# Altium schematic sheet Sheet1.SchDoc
size OrCAD D; SheetNumber: 1; SheetTotal: 1; SPICEModelCacheXSFJVCKC: <root> / <DocumentId>XSFJVCKC</DocumentId> / <CacheFrame Number="0"> / <Model Name="cap" Kind="MDL"> / <Text>*Default semiconductor capacitor / .MODEL CAP C()</Text> / </Model> / <Model Name="zener" Kind="MDL"> / <Text>*ZENER / *Default Zener 10V @ 10mA / *Zener Diode Pinout: A,K / .MODEL ZENER D( BV=10 IBV=10E-3 )</Text> / </Model> / <Model Name="led1" Kind="MDL"> / <Text>*Typ RED GaAs LED: Vf=1.7V Vr=4V If=40mA trr=3uS / *LED Pinout: 1=A, 2=K / .MODEL LED1 D (IS=93.2P RS=42M N=3.73 BV=4 IBV=10U / + CJO=2.97P VJ=.75 M=.333 TT=4.32U)</Text> / </Model> / <Model Name="1n4007" Kind="MDL"> / <Text>*1N4007 MCE 8-16-95 / *1000V 1A Si GenPurpose Diode pkg:DIODE0.4 1,2 / .MODEL 1N4007 D(IS=2.55E-9 RS=0.042 N=1.75 TT=5.76E-6 CJO=1.85E-11 / + VJ=0.75 M=0.333 BV=1000 IBV=9.86E-5 )</Text> / </Model> / </CacheFrame> / </root>
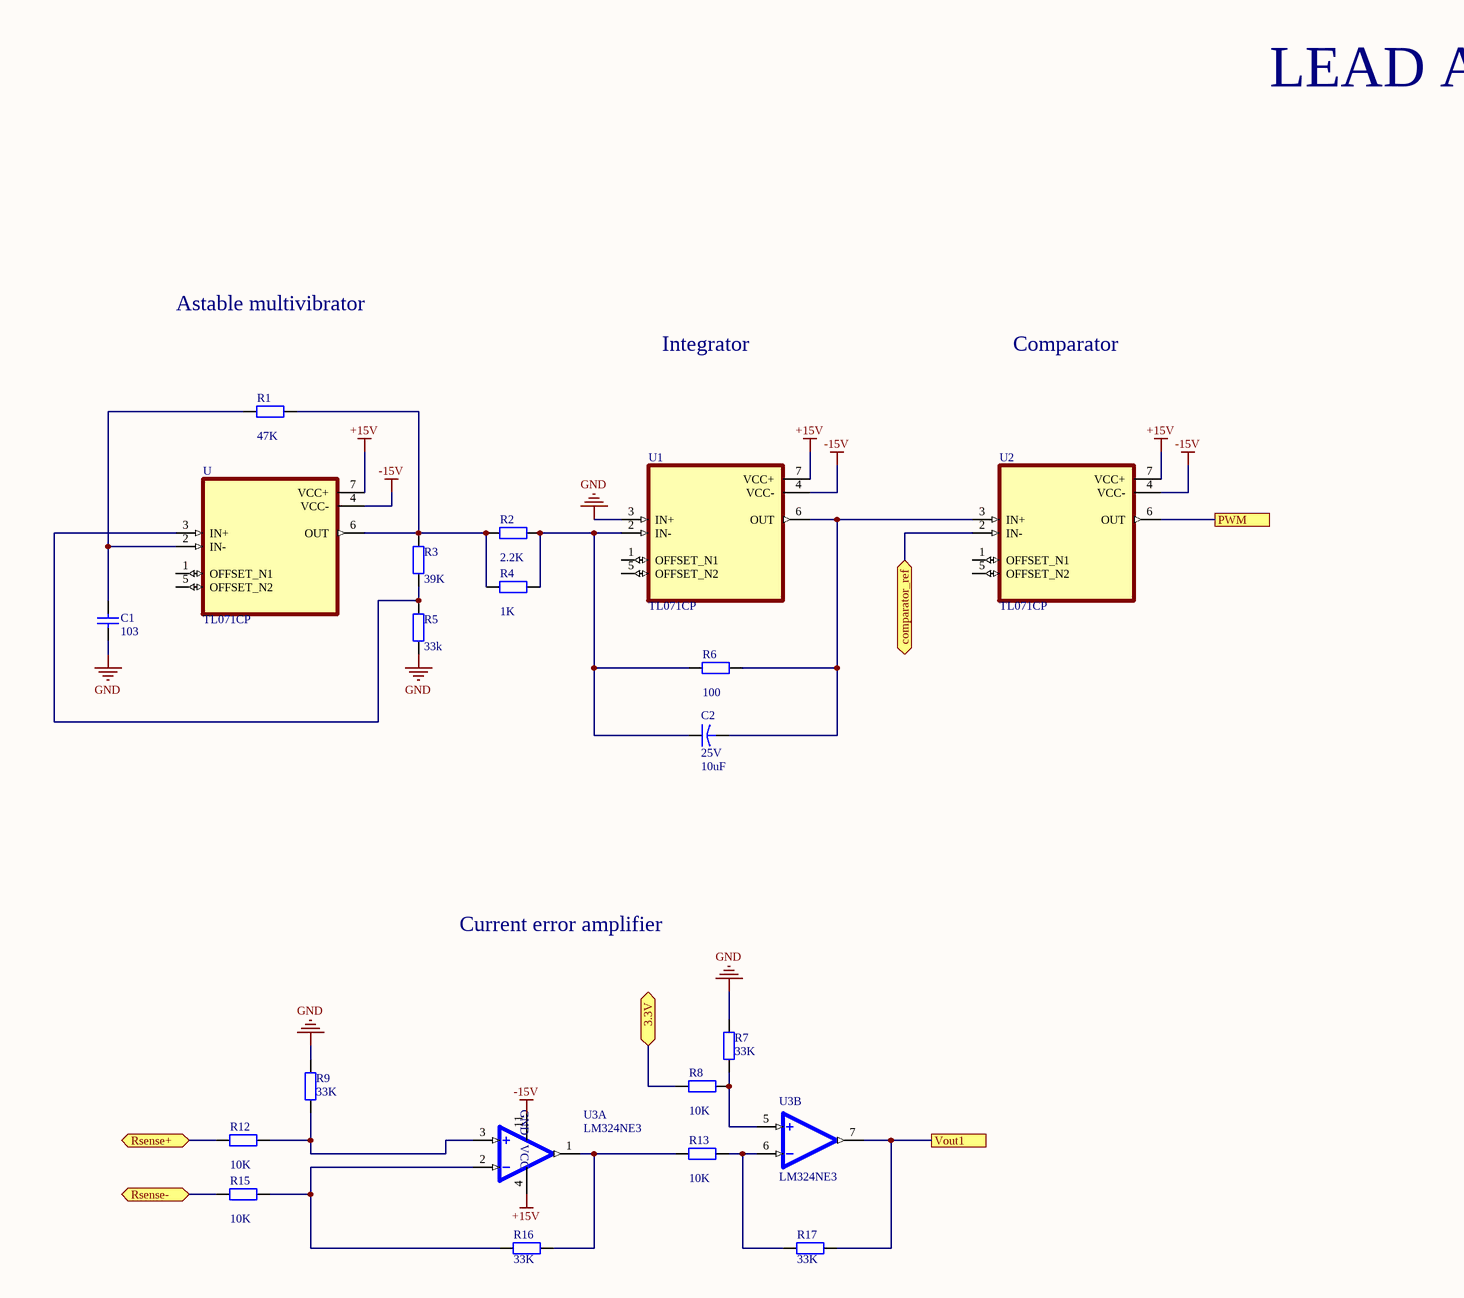
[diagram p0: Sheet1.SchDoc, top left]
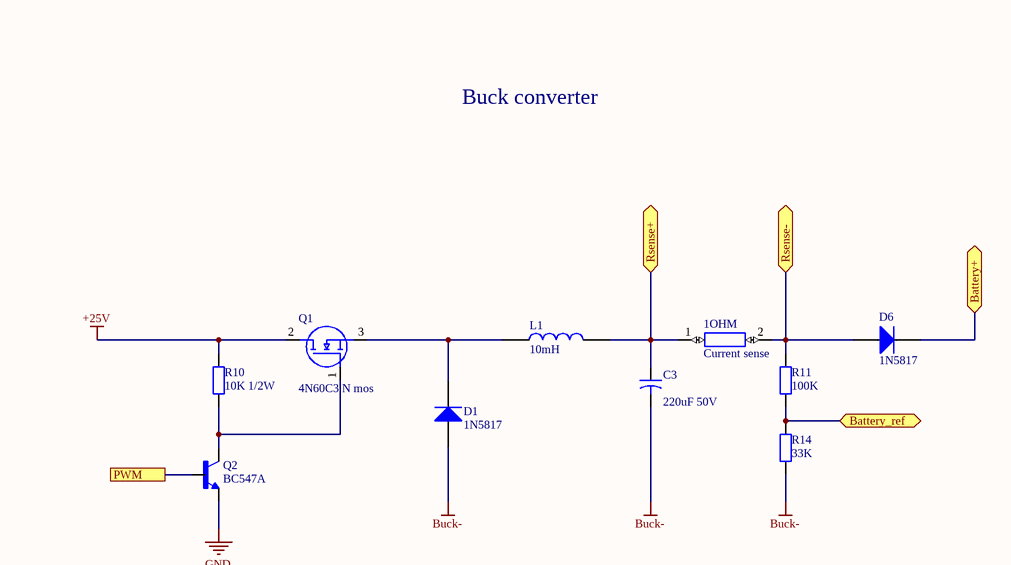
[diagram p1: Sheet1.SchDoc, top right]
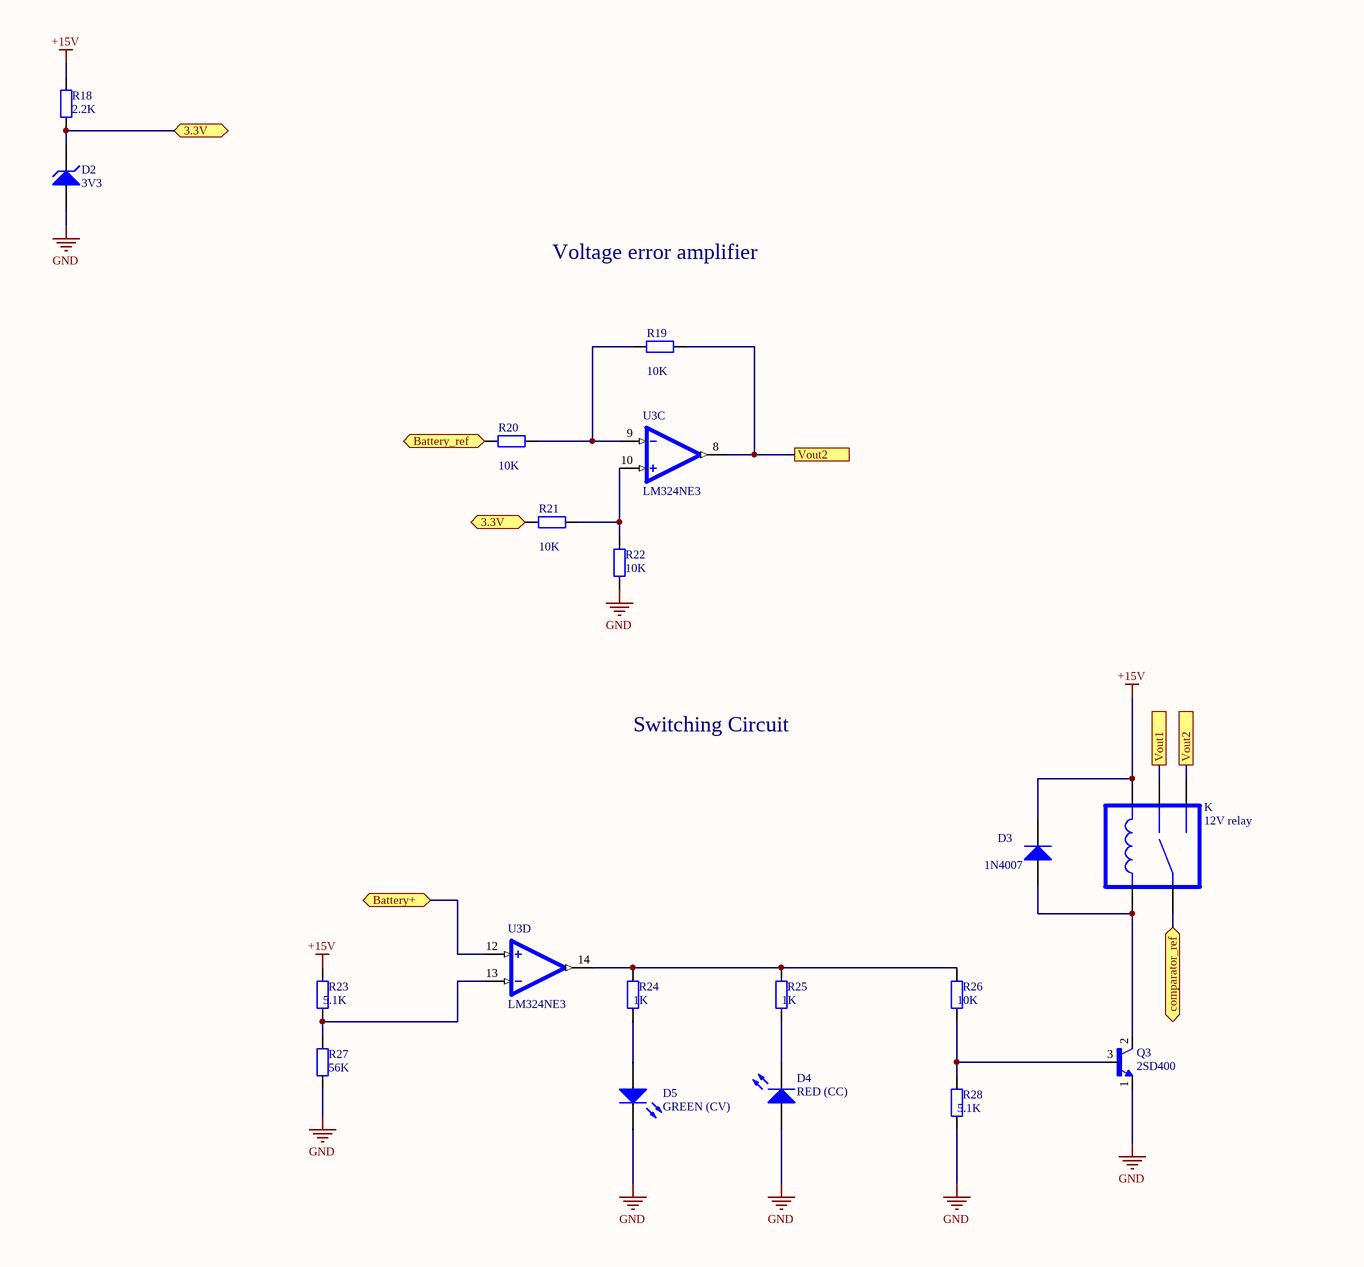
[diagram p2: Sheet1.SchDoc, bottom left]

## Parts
1OHM  Current sense  [RESAD5860W102L2380D870]
C1  103  [RAD-0.3]
C2  25V  value 10uF  [CAPR5-4X5]
C3  value 220uF 50V  [CAPR5-4X5]  (hidden comment: Cap2)
D1  1N5817  [DO-41]
D2  3V3  [DIODE-0.7]
D3  1N4007  [DO-41]
D4  RED (CC)  [LED-1]
D5  GREEN (CV)  [LED-1]
D6  1N5817  [DO-41]
K  12V relay  [TE_1461069-5]
L1  10mH  [PE92102KNL]
Q1  4N60C3 N mos  [TO544P516X1586X2557-3P]
Q2  BC547A  [TO92250P510H770-3]
Q3  2SD400  [TO92250P510H770-3]
R1  value 47K  [AXIAL-0.4]  (hidden comment: Res2)
R2  value 2.2K  [AXIAL-0.4]  (hidden comment: Res2)
R3  value 39K  [AXIAL-0.4]  (hidden comment: Res2)
R4  value 1K  [AXIAL-0.4]  (hidden comment: Res2)
R5  value 33k  [AXIAL-0.4]  (hidden comment: Res2)
R6  value 100  [AXIAL-0.4]  (hidden comment: Res2)
R7  value 33K  [AXIAL-0.4]  (hidden comment: Res2)
R8  value 10K  [AXIAL-0.4]  (hidden comment: Res2)
R9  value 33K  [AXIAL-0.4]  (hidden comment: Res2)
R10  value 10K 1/2W  [AXIAL-0.4]  (hidden comment: Res2)
R11  value 100K  [AXIAL-0.4]  (hidden comment: Res2)
R12  value 10K  [AXIAL-0.4]  (hidden comment: Res2)
R13  value 10K  [AXIAL-0.4]  (hidden comment: Res2)
R14  value 33K  [AXIAL-0.4]  (hidden comment: Res2)
R15  value 10K  [AXIAL-0.4]  (hidden comment: Res2)
R16  value 33K  [AXIAL-0.4]  (hidden comment: Res2)
R17  value 33K  [AXIAL-0.4]  (hidden comment: Res2)
R18  value 2.2K  [AXIAL-0.4]  (hidden comment: Res2)
R19  value 10K  [AXIAL-0.4]  (hidden comment: Res2)
R20  value 10K  [AXIAL-0.4]  (hidden comment: Res2)
R21  value 10K  [AXIAL-0.4]  (hidden comment: Res2)
R22  value 10K  [AXIAL-0.4]  (hidden comment: Res2)
R23  value 5.1K  [AXIAL-0.4]  (hidden comment: Res2)
R24  value 1K  [AXIAL-0.4]  (hidden comment: Res2)
R25  value 1K  [AXIAL-0.4]  (hidden comment: Res2)
R26  value 10K  [AXIAL-0.4]  (hidden comment: Res2)
R27  value 56K  [AXIAL-0.4]  (hidden comment: Res2)
R28  value 5.1K  [AXIAL-0.4]  (hidden comment: Res2)
U  TL071CP  [DIP794W45P254L959H508Q8]
U1  TL071CP  [DIP794W45P254L959H508Q8]
U2  TL071CP  [DIP794W45P254L959H508Q8]
U3  LM324NE3  [DIP794W45P254L1969H508Q14]  (parts A,B,C,D of 4)

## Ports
3.3V (bidir), Battery+ (bidir), Battery_ref (bidir), comparator_ref (bidir), PWM, Rsense+ (bidir), Rsense- (bidir), Vout1, Vout2

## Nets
+15V: D3.2(K) K.5(M2) R18.2 R23.2 U.7(VCC+) U1.7(VCC+) U2.7(VCC+) U3.4(VCC)
+25V: Q1.2(D) R10.1
-15V: U.4(VCC-) U1.4(VCC-) U2.4(VCC-) U3.11(GND)
Buck-: C3.2 D1.1(A) R14.2
GND: C1.1 D2.1(A) D4.1(A) D5.2(K) Q2.3(E) Q3.1(E) R5.1 R7.1 R9.2 R22.1 R27.1 R28.1 U1.3(IN+)
3.3V: D2.2(K) R8.1 R18.1 R21.1 ; port 3.3V
Battery+: D6.2(K) U3.12(4IN+) ; port Battery+
Battery_ref: R11.2 R14.1 R20.1 ; port Battery_ref
comparator_ref: K.1(C) U2.2(IN-) ; port comparator_ref
PWM: Q2.2(B) U2.6(OUT) ; port PWM
Rsense+: 1OHM.1 C3.1 L1.2 R12.1 ; port Rsense+
Rsense-: 1OHM.2 D6.1(A) R11.1 R15.1 ; port Rsense-
Vout1: K.4(NC) R17.1 U3.7(2OUT) ; port Vout1
Vout2: K.3(NO) R19.2 U3.8(3OUT) ; port Vout2
NetC1_2: C1.2 R1.1 U.2(IN-)
NetC2_1: C2.1 R2.2 R4.2 R6.1 U1.2(IN-)
NetC2_2: C2.2 R6.2 U1.6(OUT) U2.3(IN+)
NetD1_2: D1.2(K) L1.1 Q1.3(S)
NetD3_1: D3.1(A) K.2(M1) Q3.2(C)
NetD4_2: D4.2(K) R25.1
NetD5_1: D5.1(A) R24.1
NetQ1_1: Q1.1(G) Q2.1(C) R10.2
NetQ3_3: Q3.3(B) R26.1 R28.2
NetR1_2: R1.2 R2.1 R3.2 R4.1 U.6(OUT)
NetR3_1: R3.1 R5.2 U.3(IN+)
NetR7_2: R7.2 R8.2 U3.5(2IN+)
NetR9_1: R9.1 R12.2 U3.3(1IN+)
NetR13_1: R13.1 R16.1 U3.1(1OUT)
NetR13_2: R13.2 R17.2 U3.6(2IN-)
NetR15_2: R15.2 R16.2 U3.2(1IN-)
NetR19_1: R19.1 R20.2 U3.9(3IN-)
NetR21_2: R21.2 R22.2 U3.10(3IN+)
NetR23_1: R23.1 R27.2 U3.13(4IN-)
NetR24_2: R24.2 R25.2 R26.2 U3.14(4OUT)

Not connected (* = marked no-connect by the designer): U 1(OFFSET_N1) 5(OFFSET_N2); U1 1(OFFSET_N1) 5(OFFSET_N2); U2 1(OFFSET_N1) 5(OFFSET_N2)

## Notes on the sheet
- LEAD ACID BATTERY CHARGER
- Astable multivibrator
- Integrator
- Comparator
- Buck converter
- Current error amplifier
- Voltage error amplifier
- Switching Circuit

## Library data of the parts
1OHM = 45F25KE: 25 kOhms Â±1% 5W Through Hole Resistor Axial Wirewound; MF: Ohmite
C1 = Cap: Capacitor
C2 C3 = Cap2: Capacitor
D1 D3 D6 = Diode 1N4007: 1 Amp General Purpose Rectifier
D2 = D Zener: Zener Diode
D4 D5 = LED1: Typical RED GaAs LED
K = 1461069-5: General Purpose Relay SPDT _1 Form C_ 12VDC Coil Through Hole; MF: TE Connectivity
L1 = PE-92102KNL: Pulse 100 uH +/-20% Leaded Inductor, 2.6A Idc, 100m Rdc; Geometry.Height: 21.59mm
Q1 = SPW24N60C3: Infineon SPW24N60C3 N-channel MOSFET Transistor, 24.3 A, 650 V, 3-Pin TO-247; Geometry.Height: 5.16mm
Q2 = BC547A: Bipolar (BJT) Transistor NPN 45 V 100 mA 300MHz 625 mW Through Hole TO-92 (TO-226); MF: ON Semiconductor
Q3 = 2SD400: TO-92MOD Transistor (NPN). Low-Frequency Power Amp, Electronic Governor Applications.; MF: LGE
R1-R28 = Res2: Resistor
U U1 U2 = TL071CP: Low-Noise JFET-Input General-Purpose Operational Amplifier 8-PDIP 0 to 70; MF: Texas Instruments
U3 = LM324NE3: Quad, 30-V, 1.2-MHz operational amplifier; MF: Texas Instruments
